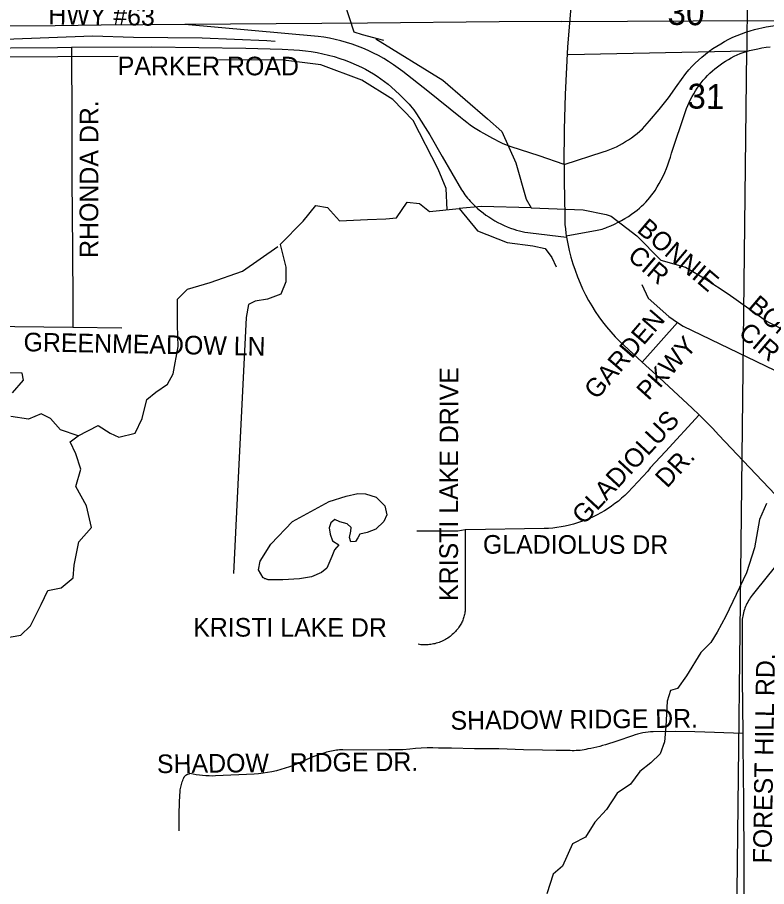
# Model space of a CAD drawing. Extents: x 1670563 to 1761545, y 515755 to 578944.
# Drawn here: x 1695996 to 1699015, y 535500 to 539003 of the extents above; entities that cross this region are included whole.
import ezdxf

# ---------------------------------------------------------------- set-up
doc = ezdxf.new("R2010")
doc.units = 0
for name, color, linetype in [('5_sectionlines', 7, 'Continuous'), ('62_text', 7, 'Continuous'), ('SHP_LINE', 7, 'Continuous'), ('STREETCL', 7, 'Continuous'), ('STRNAMES', 7, 'Continuous')]:
    doc.layers.add(name, color=color, linetype=linetype)

msp = doc.modelspace()

# ---------------------------------------------------------------- linework, layer by layer
at = {"layer": '5_sectionlines'}
for p, q in [((1698945.2, 541478.2), (1698935.3, 538868.1)), ((1698215.8, 538853.6), (1698935.3, 538868.1)), ((1695847.2, 538843.6), (1696401.9, 538846.2))]:
    msp.add_line(p, q, dxfattribs=at)
msp.add_lwpolyline([(1698933.7, 538868.1), (1698873.3, 533608.2), (1698889.2, 528322.1), (1698871.1, 523008), (1698848.1, 517668.9)], dxfattribs=at)
at = {"layer": 'SHP_LINE'}
for points in [[(1697473, 538910), (1697386, 538933), (1697353, 538944), (1697295, 539122)], [(1695112, 538904), (1695947, 538915), (1696299, 538929), (1696464, 538923), (1696740, 538921), (1697001, 538910), (1697035, 538907)], [(1697440, 538916), (1697710, 538750), (1697890, 538594), (1697948, 538543), (1698004, 538417), (1698046, 538271), (1698066, 538235)], [(1697727, 538228), (1697723, 538314), (1697691, 538391), (1697590, 538588), (1697508, 538672), (1697384, 538750), (1697218, 538812), (1697068, 538830), (1696806, 538832)], [(1697054, 538088), (1697147, 538182), (1697198, 538245), (1697246, 538237), (1697294, 538183), (1697406, 538189), (1697480, 538191), (1697524, 538195), (1697566, 538259), (1697616, 538253), (1697656, 538221), (1697776, 538233)], [(1698066, 538235), (1697866, 538241), (1697776, 538233)], [(1697776, 538233), (1697850, 538143), (1697969, 538096), (1698073, 538082), (1698123, 538072), (1698149, 538036), (1698167, 537998)], [(1698066, 538235), (1698275, 538228), (1698368, 538208), (1698388, 538202), (1698492, 538122), (1698588, 538024), (1698688, 537996), (1698770, 537948), (1698860, 537889), (1699017, 537777), (1699233, 537669), (1699347, 537616)], [(1696241, 537317), (1696321, 537359), (1696369, 537327), (1696405, 537311), (1696471, 537327), (1696499, 537387), (1696517, 537463), (1696553, 537493), (1696601, 537525), (1696623, 537567), (1696643, 537677), (1696641, 537763), (1696641, 537868), (1696681, 537908), (1696773, 537934), (1696903, 537980), (1697045, 538080)], [(1697054, 538088), (1697078, 537997), (1697078, 537937), (1697057, 537888), (1697004, 537867), (1696954, 537860), (1696927, 537846), (1696918, 537794), (1696884, 537120), (1696867, 536762)], [(1695976, 537490), (1696021, 537541), (1696015, 537569), (1695954, 537571)], [(1696241, 537317), (1696169, 537341), (1696129, 537386), (1696091, 537405), (1696040, 537384), (1695970, 537394)], [(1695940, 536502), (1696010, 536513), (1696048, 536551), (1696091, 536637), (1696118, 536693), (1696172, 536704), (1696220, 536744), (1696225, 536795), (1696244, 536889), (1696295, 536948), (1696274, 537034), (1696231, 537112), (1696252, 537182), (1696231, 537244), (1696209, 537292), (1696241, 537317)], [(1696986, 536745), (1696967, 536777), (1696974, 536811), (1697017, 536880), (1697105, 536972), (1697252, 537052), (1697320, 537074), (1697367, 537085), (1697399, 537083), (1697442, 537069), (1697477, 537034), (1697485, 536999), (1697472, 536972), (1697440, 536940), (1697405, 536927), (1697376, 536920), (1697368, 536906), (1697358, 536891), (1697340, 536889), (1697334, 536907), (1697340, 536932), (1697341, 536947), (1697324, 536962), (1697295, 536970), (1697275, 536980), (1697259, 536966), (1697252, 536946), (1697256, 536920), (1697266, 536894), (1697291, 536877), (1697274, 536858), (1697263, 536831), (1697243, 536784), (1697221, 536766), (1697181, 536749), (1697133, 536740), (1697065, 536737), (1697016, 536737), (1697014, 536737), (1697012, 536737), (1697010, 536737), (1697008, 536737), (1697006, 536737), (1697004, 536738), (1697002, 536738), (1697000, 536739), (1696999, 536739), (1696997, 536740), (1696995, 536740), (1696993, 536741), (1696991, 536742), (1696990, 536743), (1696988, 536744), (1696986, 536745)], [(1699015, 537044), (1698986, 536979), (1698966, 536866), (1698934, 536764), (1698892, 536678), (1698851, 536590), (1698815, 536526), (1698790, 536484), (1698750, 536443), (1698692, 536350), (1698656, 536298), (1698628, 536291), (1698614, 536248), (1698609, 536146), (1698604, 536084), (1698586, 536035), (1698548, 535999), (1698504, 535964), (1698466, 535913), (1698412, 535877), (1698369, 535811), (1698322, 535760), (1698285, 535700), (1698232, 535672), (1698193, 535583), (1698155, 535550), (1698129, 535471)]]:
    msp.add_lwpolyline(points, dxfattribs=at)
at = {"layer": 'STREETCL'}
for points in [[(1698198.7, 538410.7), (1698199.9, 538551.5), (1698204.2, 538692.2), (1698214.5, 538884.8), (1698229.4, 539077.1), (1698239.7, 539175.8), (1698253, 539274.1), (1698286.6, 539463.6), (1698308, 539599.8)], [(1696670.7, 538973.8), (1696333.5, 538971), (1696148, 538969.5), (1695470.7, 538964.4), (1695374.3, 538964.4), (1694484.4, 538957.6), (1694324.4, 538956.2), (1694203.3, 538957), (1694082.3, 538961.6), (1693950.7, 538967.5), (1693790.3, 538979.4), (1693688.8, 538989.6), (1693541.6, 539006.6), (1693384.7, 539029.7), (1693231.4, 539056.3), (1693085.7, 539084.6)], [(1698190.1, 538986.5), (1697937.8, 538985), (1697406.9, 538979.9), (1696670.7, 538973.8)], [(1698198.7, 538410.7), (1698098.5, 538445.3), (1697986, 538481.5), (1697974.9, 538485.2), (1697964, 538489.3), (1697953.3, 538493.8), (1697942.6, 538498.6), (1697932.2, 538503.7), (1697921.9, 538509.2), (1697911.8, 538514.9), (1697875.1, 538534.6), (1697860.9, 538542.5), (1697846.9, 538550.9), (1697833.3, 538559.8), (1697819.9, 538569), (1697806.9, 538578.8), (1697794.2, 538588.9), (1697781.9, 538599.5), (1697650, 538705.1), (1697549.1, 538784.9), (1697530.5, 538798.9), (1697511.4, 538812.4), (1697491.8, 538825.1), (1697471.8, 538837.2), (1697451.5, 538848.7), (1697430.7, 538859.4), (1697409.6, 538869.4), (1697388.2, 538878.7), (1697366.4, 538887.2), (1697344.4, 538895), (1697322.1, 538902.1), (1697299.6, 538908.4), (1697276.9, 538913.9), (1697254.1, 538918.7), (1697231.1, 538922.7), (1697207.9, 538925.8), (1696670.7, 538973.8)], [(1698190.1, 538986.5), (1698719, 538988.9), (1699183.1, 538990)], [(1698198.7, 538410.7), (1698356.5, 538460.9), (1698370, 538465.4), (1698383.3, 538470.5), (1698396.4, 538475.9), (1698409.3, 538481.9), (1698422, 538488.3), (1698434.5, 538495.1), (1698446.8, 538502.3), (1698458.7, 538510), (1698470.4, 538518.1), (1698481.9, 538526.6), (1698493, 538535.5), (1698503.8, 538544.8), (1698514.2, 538554.4), (1698524.3, 538564.4), (1698534.1, 538574.8), (1698543.5, 538585.5), (1698581.8, 538631.9), (1698618.9, 538679.4), (1698654.6, 538727.9), (1698689, 538777.4), (1698701.1, 538791.4), (1698713.8, 538805), (1698726.8, 538818.2), (1698740.3, 538830.9), (1698754.3, 538843.2), (1698768.6, 538854.9), (1698783.3, 538866.2), (1698798.4, 538877), (1698813.9, 538887.2), (1698829.7, 538896.9), (1698845.8, 538906.1), (1698862.3, 538914.7), (1698879, 538922.8), (1698896, 538930.2), (1698913.2, 538937.1), (1698930.6, 538943.4), (1698948.3, 538949.1), (1698966.1, 538954.3), (1699013.1, 538965.2), (1699183.1, 538990)], [(1695644.5, 538877.9), (1695779, 538878.9), (1696157.1, 538881.9), (1696213.8, 538882.3)], [(1696213.8, 538882.3), (1696538, 538884.7), (1696916.1, 538878.6), (1697062.2, 538875), (1697109.4, 538872.6), (1697133, 538871), (1697156.5, 538868.6), (1697179.9, 538865.4), (1697203.1, 538861.4), (1697226.3, 538856.7), (1697249.2, 538851.2), (1697272, 538844.9), (1697294.5, 538837.9), (1697316.8, 538830.1), (1697338.8, 538821.6), (1697360.5, 538812.4), (1697381.9, 538802.4), (1697398.3, 538794.2), (1697414.3, 538785.3), (1697430.1, 538775.9), (1697445.5, 538766), (1697460.5, 538755.6), (1697475.2, 538744.7), (1697489.5, 538733.2), (1697503.5, 538721.3), (1697535.7, 538691.7), (1697567, 538661.1), (1697573.9, 538653.8), (1697580.5, 538646.3), (1697586.9, 538638.6), (1697593.1, 538630.6), (1697598.9, 538622.5), (1697604.5, 538614.1), (1697657.2, 538529), (1697707.4, 538442.5), (1697785.8, 538308.7), (1697790.1, 538301.6), (1697794.6, 538294.7), (1697799.3, 538288), (1697804.2, 538281.3), (1697809.3, 538274.9), (1697814.7, 538268.6), (1697820.2, 538262.5), (1697830, 538252.3), (1697840.1, 538242.5), (1697850.5, 538233), (1697861.3, 538223.8), (1697872.4, 538215), (1697883.7, 538206.6), (1697895.3, 538198.6), (1697907.2, 538190.9), (1697919.3, 538183.7), (1697931.6, 538176.9), (1697944.2, 538170.4), (1697957, 538164.4), (1697970, 538158.9), (1697983.1, 538153.7), (1697996.4, 538149), (1698007.4, 538145.6), (1698018.6, 538142.7), (1698029.8, 538140.1), (1698041.1, 538137.9), (1698052.5, 538136.1), (1698064, 538134.8), (1698208.3, 538117.8)], [(1696213.8, 538882.3), (1696214.5, 538577.5), (1696215.1, 538333.6), (1696217.1, 538225.1), (1696219, 537871.5), (1696219.7, 537754.6)], [(1698207.5, 538122.1), (1698331.7, 538145.1), (1698338.8, 538146.5), (1698345.8, 538148.2), (1698352.7, 538150.1), (1698359.5, 538152.2), (1698366.3, 538154.6), (1698373, 538157.1), (1698387.7, 538163.3), (1698402.2, 538170), (1698416.4, 538177.1), (1698430.4, 538184.7), (1698444.2, 538192.7), (1698457.7, 538201.1), (1698470.9, 538210), (1698483.8, 538219.3), (1698493.2, 538226.6), (1698502.4, 538234.3), (1698511.3, 538242.2), (1698520, 538250.5), (1698528.3, 538259), (1698536.4, 538267.9), (1698544.1, 538277), (1698551.5, 538286.4), (1698558.5, 538296), (1698565.3, 538305.9), (1698574.1, 538319.9), (1698582.4, 538334.1), (1698590.3, 538348.6), (1698597.7, 538363.4), (1698604.7, 538378.4), (1698611.1, 538393.6), (1698617.1, 538409), (1698622.5, 538424.6), (1698627.5, 538440.3), (1698631.9, 538456.2), (1698688.1, 538623.3), (1698692.5, 538635.8), (1698697.4, 538648.1), (1698702.7, 538660.2), (1698708.4, 538672.2), (1698714.5, 538683.9), (1698721, 538695.5), (1698727.9, 538706.8), (1698735.2, 538717.8), (1698742.9, 538728.6), (1698751, 538739.2), (1698759.4, 538749.4), (1698768.1, 538759.4), (1698777.2, 538769), (1698786.6, 538778.3), (1698796.3, 538787.3), (1698806.4, 538796), (1698816.7, 538804.3), (1698827.3, 538812.2), (1698838.2, 538819.8), (1698849.3, 538827), (1698860.7, 538833.8), (1698872.3, 538840.2), (1698884.1, 538846.2), (1698896.1, 538851.8), (1698908.3, 538856.9), (1698920.7, 538861.7), (1698933.2, 538866), (1698945.9, 538869.9), (1698979.3, 538876.8), (1698996.1, 538879.9), (1699012.9, 538882.5), (1699029.8, 538884.6)], [(1698198.7, 538410.7), (1698199.2, 538343.3), (1698201.1, 538204.1), (1698201.5, 538186.4), (1698202.4, 538168.8), (1698203.8, 538151.3), (1698205.7, 538133.7), (1698207.5, 538122.1)], [(1698207.5, 538122.1), (1698208.3, 538117.8)], [(1698208.3, 538117.8), (1698213.4, 538090.6), (1698219.4, 538063.5), (1698226.4, 538036.7), (1698234.2, 538010.2), (1698242.9, 537983.9), (1698252.5, 537957.9), (1698263, 537932.3), (1698273.6, 537908.6), (1698285, 537885.3), (1698297.2, 537862.5), (1698310.3, 537840), (1698324.1, 537818.1), (1698338.6, 537796.6), (1698353.9, 537775.7), (1698369.9, 537755.3), (1698386.6, 537735.4), (1698404, 537716.2), (1698422.1, 537697.6), (1698513.9, 537613.2)], [(1698512.3, 537926.6), (1698537, 537872.1), (1698621.3, 537797.6), (1698656.3, 537773.4)], [(1695750, 537760.4), (1696219.7, 537754.6)], [(1696219.7, 537754.6), (1696417.2, 537752.2)], [(1698513.9, 537613.2), (1698656.3, 537773.4)], [(1698656.3, 537773.4), (1698678.3, 537758.2), (1699083.2, 537563.6)], [(1698513.9, 537613.2), (1698582.7, 537550.1), (1698715.1, 537428), (1698743.5, 537401)], [(1698743.5, 537401), (1698608, 537254.1), (1698546, 537187.5), (1698535.8, 537173.9), (1698455.5, 537088.2), (1698443.2, 537076.4), (1698430.5, 537065), (1698417.4, 537054.1), (1698403.9, 537043.7), (1698390.1, 537033.6), (1698376, 537024.1), (1698361.5, 537015.1), (1698346.8, 537006.5), (1698331.8, 536998.5), (1698316.5, 536990.9), (1698301, 536983.9), (1698285.2, 536977.4), (1698269.2, 536971.5), (1698253.1, 536966.1), (1698236.8, 536961.2), (1698220.3, 536956.9), (1698203.6, 536953.1), (1698186.9, 536950), (1698170.1, 536947.4), (1698153.1, 536945.3), (1698136.2, 536943.8), (1698119.1, 536943), (1697803.3, 536938.5), (1697800.3, 536938)], [(1698743.5, 537401), (1698770.3, 537374.4), (1698796.4, 537347.1), (1698821.9, 537319.2), (1698946.1, 537189.6), (1699129, 536997), (1699177, 536946)], [(1697800.3, 536938), (1697771, 536933.1), (1697604.7, 536932.1)], [(1697800.3, 536938), (1697800.3, 536615.5), (1697799.8, 536610.8), (1697799.3, 536606.1), (1697798.5, 536601.5), (1697797.6, 536596.8), (1697796.5, 536592.3), (1697795.3, 536587.7), (1697794, 536583.2), (1697792.4, 536578.8), (1697790.7, 536574.4), (1697788.9, 536570), (1697786.9, 536565.7), (1697784.8, 536561.5), (1697782.5, 536557.4), (1697780.1, 536553.4), (1697777.6, 536549.4), (1697774.9, 536545.5), (1697771.6, 536540.9), (1697768.1, 536536.4), (1697764.4, 536532.1), (1697760.6, 536527.8), (1697756.7, 536523.7), (1697752.6, 536519.7), (1697748.4, 536515.9), (1697744.1, 536512.2), (1697739.6, 536508.6), (1697735, 536505.3), (1697730.3, 536502), (1697725.5, 536499), (1697720.6, 536496.1), (1697715.6, 536493.3), (1697710.5, 536490.8), (1697705.4, 536488.4), (1697700.1, 536486.2), (1697694.8, 536484.2), (1697689.4, 536482.3), (1697683.9, 536480.7), (1697678.4, 536479.2), (1697672.9, 536477.9), (1697667.3, 536476.9), (1697661.7, 536476), (1697656, 536475.3), (1697650.4, 536474.7), (1697644.7, 536474.4), (1697639, 536474.3), (1697633.3, 536474.4), (1697627.6, 536474.7), (1697621.9, 536475.1), (1697616.2, 536475.8), (1697610.6, 536476.6)], [(1699177, 536946), (1699021.9, 536756.3), (1698957, 536674.6), (1698953, 536669.3), (1698949.1, 536663.9), (1698945.4, 536658.4), (1698942, 536652.7), (1698938.7, 536646.9), (1698935.6, 536641), (1698932.8, 536635), (1698930.1, 536628.9), (1698927.7, 536622.7), (1698925.4, 536616.4), (1698923.4, 536610.1), (1698921.7, 536603.7), (1698920.1, 536597.2), (1698918.8, 536590.7), (1698917.7, 536584.1), (1698916.8, 536577.5), (1698916.2, 536570.9), (1698917, 536338.4), (1698919.1, 536117.7)], [(1698919.1, 536117.7), (1698805, 536121), (1698765.5, 536123.1), (1698725.9, 536124), (1698647.2, 536125.2), (1698558.2, 536124.4), (1698547.5, 536123.7), (1698537, 536122.6), (1698526.4, 536121.1), (1698515.9, 536119.3), (1698505.5, 536117.1), (1698495.2, 536114.5), (1698485, 536111.6), (1698474.8, 536108.3), (1698411.2, 536086.1), (1698365.5, 536072.2), (1698354, 536068.3), (1698342.4, 536064.8), (1698330.6, 536061.7), (1698318.8, 536059.1), (1698306.8, 536056.8), (1698294.8, 536055), (1698287, 536053.2), (1698279.1, 536051.6), (1698271.2, 536050.4), (1698263.2, 536049.3), (1698255.2, 536048.6), (1698247.1, 536048.1), (1698239.1, 536047.8), (1698231.1, 536047.8), (1698223, 536048.1), (1698167.4, 536048.3), (1698111.9, 536049.8), (1698035.6, 536051.4), (1697936.1, 536054.9), (1697838.1, 536056.1), (1697745.6, 536057.7), (1697718.9, 536058.5), (1697692.2, 536058.3), (1697669.3, 536059), (1697646.4, 536058.9), (1697623.5, 536057.9), (1697600.6, 536056.2), (1697577.8, 536053.7), (1697549.6, 536051.8), (1697521.3, 536050.9), (1697493.1, 536050.9), (1697391.4, 536050.2), (1697307.8, 536051.5), (1697301.1, 536051.4), (1697294.4, 536051.2), (1697287.7, 536050.7), (1697281, 536050), (1697274.3, 536049.1), (1697267.7, 536048), (1697261.1, 536046.7), (1697254.6, 536045.2), (1697248.1, 536043.4), (1697241.7, 536041.4), (1697235.3, 536039.3), (1697186.5, 536022.8), (1697108.8, 535988.9), (1697091.7, 535982.6), (1697074.4, 535976.9), (1697056.9, 535971.8), (1697039.3, 535967.2), (1697021.6, 535963.1), (1697003.7, 535959.7), (1696985.8, 535956.8), (1696967.7, 535954.4), (1696949.6, 535952.7), (1696794, 535946.2), (1696781.1, 535945.9), (1696768.1, 535946), (1696755.2, 535946.6), (1696742.3, 535947.5), (1696729.4, 535948.9), (1696716.6, 535950.8), (1696703.9, 535953), (1696691.2, 535955.7)], [(1698919.1, 536117.7), (1698919.6, 536071.7), (1698921.7, 535840.4), (1698923.4, 535605.2), (1698922.5, 535368.8), (1698923.1, 535287.8)], [(1696647.3, 535724.7), (1696648.1, 535797.9), (1696650.8, 535871), (1696651.3, 535878.4), (1696651.7, 535884.1), (1696652.3, 535889.8), (1696653.2, 535895.4), (1696654.2, 535901), (1696655.4, 535906.6), (1696656.8, 535912.2), (1696658.4, 535917.6), (1696660.2, 535923.1), (1696662.2, 535928.4), (1696664.3, 535933.7), (1696666.6, 535938.9), (1696667.1, 535939.8), (1696667.6, 535940.7), (1696668.1, 535941.6), (1696668.6, 535942.4), (1696669.2, 535943.3), (1696669.7, 535944.1), (1696670.4, 535944.9), (1696671, 535945.6), (1696671.7, 535946.4), (1696672.4, 535947.1), (1696673.1, 535947.8), (1696673.8, 535948.5), (1696674.6, 535949.2), (1696675.4, 535949.8), (1696676.2, 535950.4), (1696677, 535950.9), (1696677.9, 535951.5), (1696678.8, 535952), (1696679.6, 535952.5), (1696680.5, 535952.9), (1696681.5, 535953.3), (1696682.4, 535953.7), (1696683.3, 535954.1), (1696684.3, 535954.4), (1696685.2, 535954.7), (1696686.2, 535954.9), (1696687.2, 535955.2), (1696688.2, 535955.3), (1696689.2, 535955.5), (1696690.2, 535955.6), (1696691.2, 535955.7)]]:
    msp.add_lwpolyline(points, dxfattribs=at)

# ---------------------------------------------------------------- texts
at = {"layer": '62_text'}
for s, rotation, p in [('30', 358.9311, (1698614.9, 538973.4)), ('31', 358.9328, (1698694.9, 538636.1))]:
    msp.add_text(s, height=100, rotation=rotation, dxfattribs=at).set_placement(p)
at = {"layer": 'STRNAMES'}
for s, rotation, p in [('HWY #63', 359.2392, (1696119.9, 538974.9)), ('PARKER ROAD', 359.9105, (1696400.1, 538770.3)), ('RHONDA DR.', 89.9105, (1696321.2, 538033.7)), ('BONNIE ', 319.6569, (1698488.1, 538141.6)), ('CIR', 319.6569, (1698450.2, 538033.2)), ('BONNIE ', 319.6569, (1698934.6, 537832)), ('GARDEN', 49.1953, (1698329.7, 537459.2)), ('CIR', 319.6569, (1698896.7, 537723.6)), ('GREENMEADOW LN', 358.9105, (1696020, 537657.8)), ('PKWY', 48.0764, (1698539.4, 537455.4)), ('KRISTI LAKE DRIVE', 89.9105, (1697770.9, 536651.5)), ('GLADIOLUS ', 47.1965, (1698278.3, 536954.5)), ('DR.', 47.1965, (1698613.8, 537102.9)), ('GLADIOLUS DR', 359.9105, (1697871.7, 536841.9)), ('KRISTI LAKE DR', 359.9105, (1696704.1, 536507.9)), ('FOREST HILL RD.', 89.0765, (1699034.6, 535593.1)), ('SHADOW RIDGE DR.', 0.5178, (1697741.4, 536132.3)), ('SHADOW   RIDGE DR.', 0.5178, (1696558.4, 535957.4))]:
    msp.add_text(s, height=75, rotation=rotation, dxfattribs=at).set_placement(p)

doc.saveas('drawing.dxf')
